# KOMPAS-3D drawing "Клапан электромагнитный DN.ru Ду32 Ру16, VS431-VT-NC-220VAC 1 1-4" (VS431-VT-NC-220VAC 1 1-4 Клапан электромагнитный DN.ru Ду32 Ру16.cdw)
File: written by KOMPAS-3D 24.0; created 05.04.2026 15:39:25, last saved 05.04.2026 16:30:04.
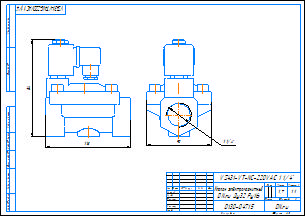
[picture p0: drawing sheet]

Document properties: c3d_UniqueCompID: ef56311e-7521-43dc-8291-0e6108b3d81d; Автор: artio; Класс точности: c; Знак неуказанной шероховатости: Шероховатость не задана; Рассекать на разрезах: Да; c3d_UniqueCompID: ef56311e-7521-43dc-8291-0e6108b3d81d; Автор: artio; Класс точности: c; Знак неуказанной шероховатости: Шероховатость не задана; Рассекать на разрезах: Да; c3d_UniqueCompID: ef56311e-7521-43dc-8291-0e6108b3d81d; Автор: artio; Класс точности: c; Знак неуказанной шероховатости: Шероховатость не задана; Рассекать на разрезах: Да; Автор: artio; Форматы листов документа: A3; Полное имя файла: VS431-VT-NC-220VAC 1 1-4 Клапан электромагнитный DN.ru Ду32 Ру16.m3d; Масса: 1.701; Наименование: Клапан электромагнитный DN.ru Ду32 Ру16; Количество листов документа: 1; Примечание: D130-04715

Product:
- Body: Тело 1  | qty 1
    Масса: 3.709873
- Part/product: Клапан электромагнитный DN.ru Ду32 Ру16  | designation VS431-VT-NC-220VAC 1 1-4
    Масса: 1.701
    Раздел спецификации: Прочие изделия
    Примечание: D130-04715
    additional columns: ef56311e-7521-43dc-8291-0e6108b3d81d; artio; c; Шероховатость не задана; Да

Views: Вид 1, Спереди
Referenced files in C:\Users\artio\OneDrive\Рабочий стол\Клапан электромагнитный DN.ru\VS431\VS431-ET-NC\: VS431-ET-NC-220VAC 3-4 Клапан электромагнитный DN.ru Ду20 Ру16.m3d, VS431-ET-NC-220VAC 3-4 Клапан электромагнитный DN.ru Ду20 Ру16.cdw
Referenced files in C:\Users\artio\OneDrive\Рабочий стол\Клапан электромагнитный DN.ru\VS431\VS431-VT-NC\: VS431-VT-NC-220VAC 1 1-4 Клапан электромагнитный DN.ru Ду32 Ру16.m3d
Referenced files in C:\Users\artio\OneDrive\Рабочий стол\Клапан электромагнитный DN.ru\VS431\VS431-VT-NC\VS431-VT-NC-220VAC\Ду32\: VS431-VT-NC-220VAC 1 1-4 Клапан электромагнитный DN.ru Ду32 Ру16.m3d
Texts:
  VS431-VT-NC-220VAC 1 1-4
  Клапан электромагнитный
  DN.ru Ду32 Ру16
  VS431-VT-NC-220VAC 1 1/4"
  VS431-VT-NC-220VAC 1 1/4"-
  Клапан электромагнитный DN.ru Ду32 Ру16
  VS431-VT-NC-220VAC 1 1-4 Клапан электромагнитный DN.ru Ду32 Ру16
Dimensions and other numbers on the sheet: 0; 3; 2; 4; 90; 1 1/4"; 1:1; 1; 1,7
